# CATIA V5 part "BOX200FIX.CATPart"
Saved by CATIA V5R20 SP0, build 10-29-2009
Part number: BOX200FIX
Bounding box of the stored display mesh (mm): x 0 to 326, y -20 to 55, z -40 to 15
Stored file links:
  C:\Users\Utente\Desktop\IO LAVORO\3D X SITO CF\X SITO\PLASTICA\BOX\BOX200FIX.CATPart
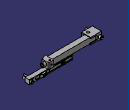
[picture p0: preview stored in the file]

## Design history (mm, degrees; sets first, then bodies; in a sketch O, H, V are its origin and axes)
Set1
  DatumSurface1 to DatumSurface16 "_ZH90/2_head"
  DatumSurface17 to DatumSurface34 "_ZH90/2_screw1"
  DatumSurface35 to DatumSurface55 "_ZH90/2_hand"
  DatumSurface56 to DatumSurface73 "_ZH90/2_screw2"
  DatumSurface74 to DatumSurface94 "_ZH90/2_he"
  DatumSurface95 to DatumSurface109 "_ZH90/2_screw3"
  DatumSurface110 to DatumSurface117 "_ZH90/2_stift1"
  DatumSurface118 to DatumSurface127 "_ZH90/2_stift2"
  DatumSurface128 to DatumSurface160 "_ZH90/03_body"
  DatumSurface161 to DatumSurface178 "_M8-5"
  DatumSurface179 to DatumSurface198 "_ST2"
  DatumSurface199 to DatumSurface213 "_ZH90/03_foot3"
  DatumSurface214 to DatumSurface230 "_M6-3"
  DatumSurface231 to DatumSurface248 "_M6-4"
  DatumSurface249 to DatumSurface260 "_ZH90/03_foot4"
  DatumSurface261 to DatumSurface280 "_ST1"
Body1 (main body)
